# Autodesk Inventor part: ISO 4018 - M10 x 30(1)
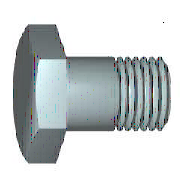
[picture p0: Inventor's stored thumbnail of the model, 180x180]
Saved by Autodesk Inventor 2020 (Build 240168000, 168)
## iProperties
Created: 2019-01
Part Number: ISO 4018 - M10 x 30(1)
Material: Ocel
Description: Šrouby se šestihrannou hlavou se závitem k hlavě. Výrobní třída C
Document SubType Name: Modeling
Standard: ISO 4018
Designer: doma
Standard Revision: Fourth edition 2011-04-01
Standards Organization: ISO
Language: cs-CZ
Size Designation: M10 x 30
Categories: <MemberInstance><Categories><Category DisplayName="Spojovací materiál" InternalName="e4da775c-781d-43d5-af7c-5136215cf5a6" Mnemonic="FSTN"><Category DisplayName
Density: 7.85 g/cm^3
Appearance: Plech
IsCustomPart: 0
Author: doma
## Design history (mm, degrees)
node "WorkPlane1"
node "WorkPoint1"
node "MSC_A1"
node "MSC_PF1"
node "MSC_PT1"
body "Solid1"
node "Náčrt1"
sketch "Náčrt2"
  geometry: L1 (-8, 4.619)-(-8, -4.619); L2 (0, 9.237)-(-8, 4.619); L3 (8, 4.619)-(0, 9.237); L4 (8, -4.619)-(8, 4.619); L5 (0, -9.237)-(8, -4.619); L6 (-8, -4.619)-(0, -9.237); C1 r 8 at (0, 0); 1 further point
  constraints: 12 end point, 6 tangent, 2 parallel, 2 vertical, 1 centre point
  dimensions: "d1" = 16 diameter of C1 (= ParS); "d29" = 0 distance of point (0, 0) C1.centre; "d30" = 0 distance of C1.centre point (0, 0)
extrude "Vysunutí1" new body sketch "Náčrt2" distance "d6" = 6.4 (= ParK); taper "d7" = 0 deg
revolve "Rotace1" stored, may be unused: angle "d14" = 360 deg
revolve "Rotace2" stored, may be unused: angle "d21" = 360 deg
chamfer "Zkosení1" distance "d22" = 0.75 (= 0.5 x PTC); stored, may be unused: second distance "d23" = 0.75 (= 0.5 x PTC), angle "d39" = 45 deg
fillet "Zaoblení1" dims "d24" = 0.4 (= r)
feature "Závit1" dims "d32" = 0, "b" = 27 (= NLG - 2 x PTC)
sketch "Náčrt3"
  geometry: L1 (8, 6.4)-(9.337, 6.4); L2 (9.337, 5.628)-(8, 6.4); L3 (9.337, 6.4)-(9.337, 5.628); L4 (0, -1.28)-(0, 7.68) reference; L5 (9.237, 0)-(9.237, 6.4) reference
  constraints: 6 end point, 1 horizontal, 1 vertical
  dimensions: "d25" = 0.1 distance between parallel lines of L5 L3; "d26" = 0 distance from line of L5.end L1; "d27" = 60 deg angle of L3 L2; "d28" = 8 distance from line of L4 L1.start (= 0.5 x ParS)
sketch "Náčrt4"
  geometry: L1 (0, -30)-(0, 0); L2 (-5, -30)-(0, -30); L3 (-5, 0)-(-5, -30); L4 (0, 0)-(-5, 0); L5 (0, -30)-(0, 0); L6 (-6, 0)-(1, 0) reference; L7 (0, -36)-(0, 6) reference
  constraints: 10 end point, 2 horizontal, 2 vertical
  dimensions: "d18" = 5 distance of L1.start L2.start (= 0.5 x NND); "d20" = 30 distance of L3.start L2.start (= NLG); "d33" = 0 distance between parallel lines of L7 L1; "d34" = 0 distance between parallel lines of L6 L4
other parameters: "NLG" = 30 [user parameter; used in 2 equation terms], "PTC" = 1.5 [user parameter; used in 3 equation terms], "ParK" = 6.4 [user parameter; used in 1 equation term], "ParS" = 16 [user parameter; used in 3 equation terms], "msp_es" = 9.23788 (= 0.577367 x ParS) [user parameter], "r" = 0.4 [user parameter; used in 1 equation term], "d2" = 15 (derived), "d4" = 17.32102 (derived), "d8" = 15 (derived), "d10" = 0 (derived), "d12" = 30 deg (derived), "d15" = 0 (derived), "d37" = 0, "d38" = 0, "d40" = 0, "d41" = 0, "d42" = 0
